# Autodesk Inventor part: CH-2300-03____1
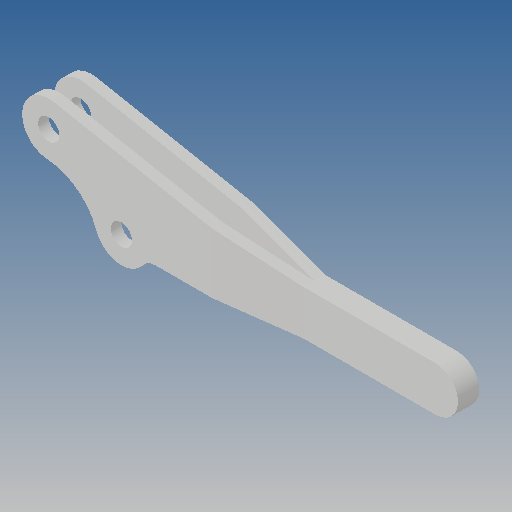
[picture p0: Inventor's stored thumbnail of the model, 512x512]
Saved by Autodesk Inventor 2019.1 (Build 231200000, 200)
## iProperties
Created: 2012-09
Part Number: CH-2300-03____1
Material: Ogólny
Document SubType Name: Modeling
Designer: CADENGINEERING4
Density: 1 g/cm^3
Appearance: Domyślna
Author: CADENGINEERING4
Revision Number: ÈÎºÎ
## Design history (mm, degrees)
feature "NONE"
node "Bryła1"
